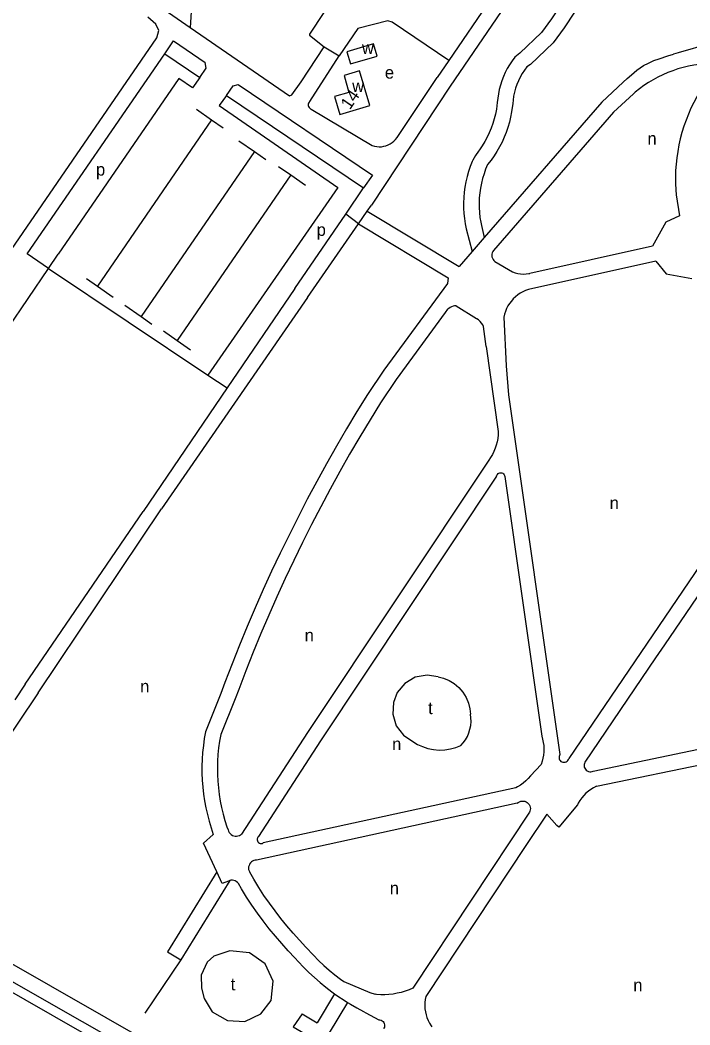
# Model space of a CAD drawing. Extents: x 157155 to 159285, y 385001 to 386651.
# Drawn here: x 158563.8 to 158780.5, y 385278.4 to 385603.8 of the extents above; entities that cross this region are included whole.
import ezdxf

# ---------------------------------------------------------------- set-up
doc = ezdxf.new("R2010")
doc.units = 0
for name, color, linetype in [('BLT_Basislijn', 7, 'Continuous'), ('BLT_Bebouwing', 7, 'Continuous'), ('BLT_Centroide', 7, 'Continuous'), ('BLT_Huisnummer', 7, 'Continuous')]:
    doc.layers.add(name, color=color, linetype=linetype)

msp = doc.modelspace()

# ---------------------------------------------------------------- linework, layer by layer
at = {"layer": 'BLT_Basislijn'}
for p, q in [((158751.68, 385654.34), (158702.89, 385582.36)), ((158602.47, 385612.76), (158618.75, 385601.38)), ((158716.17, 385610.87), (158702.45, 385590.64)), ((158787.14, 385596.2), (158776.65, 385593.14)), ((158610.55, 385592.88), (158621.93, 385585.19)), ((158657.48, 385577.4), (158667, 385592.17)), ((158662.19, 385595.07), (158667, 385592.17)), ((158725.45, 385593.04), (158723.83, 385591.7)), ((158776.65, 385593.14), (158775.15, 385592.7)), ((158702.45, 385590.64), (158698.75, 385585.17)), ((158728.91, 385589.43), (158727.74, 385588.59)), ((158702.89, 385582.36), (158677.42, 385543.88)), ((158685.75, 385565.74), (158698.75, 385585.17)), ((158758.94, 385583.66), (158751.98, 385577.17)), ((158762.2, 385579.88), (158755.75, 385573.89)), ((158751.98, 385577.17), (158713.92, 385533.36)), ((158718.17, 385577.11), (158717.88, 385574.87)), ((158723.15, 385576.76), (158722.81, 385574.03)), ((158620.8, 385574.96), (158625.74, 385571.48)), ((158657.95, 385574.91), (158677.67, 385563.1)), ((158755.75, 385573.89), (158716.92, 385529.2)), ((158625.74, 385571.48), (158588.77, 385517.6)), ((158625.74, 385571.48), (158629.45, 385568.87)), ((158634.58, 385564.7), (158639.59, 385561.17)), ((158639.59, 385561.17), (158602.95, 385507.76)), ((158639.59, 385561.17), (158643.24, 385558.6)), ((158647.41, 385556.36), (158651.33, 385553.6)), ((158716.15, 385558.36), (158715.02, 385556.95)), ((158651.33, 385553.6), (158614.58, 385500.04)), ((158651.33, 385553.6), (158656.07, 385550.26)), ((158676.06, 385541.9), (158677.42, 385543.88)), ((158673.21, 385537.78), (158669.11, 385540.93)), ((158673.21, 385537.78), (158676.06, 385541.9)), ((158676.06, 385541.9), (158705.8, 385524.02)), ((158656.75, 385513.98), (158673.21, 385537.78)), ((158673.21, 385537.78), (158702.3, 385520.29)), ((158713, 385537.22), (158713.92, 385533.36)), ((158708.12, 385536.14), (158710.01, 385528.86)), ((158713.92, 385533.36), (158710.01, 385528.86)), ((158768.43, 385530.57), (158728.67, 385521.7)), ((158572.92, 385523.29), (158576.09, 385528)), ((158710.01, 385528.86), (158705.8, 385524.02)), ((158717.32, 385525.64), (158723.07, 385522.22)), ((158769.51, 385525.69), (158728.23, 385516.48)), ((158559.8, 385503.88), (158572.92, 385523.29)), ((158572.92, 385523.29), (158624.56, 385488.81)), ((158585.21, 385520.11), (158588.77, 385517.6)), ((158588.77, 385517.6), (158593.87, 385514.01)), ((158656.75, 385513.98), (158609.48, 385445.45)), ((158652.62, 385516.8), (158630.77, 385484.66)), ((158597.71, 385511.45), (158602.95, 385507.76)), ((158704.89, 385511.19), (158711.42, 385507.15)), ((158602.95, 385507.76), (158606.37, 385505.35)), ((158701.31, 385509.03), (158685.43, 385487.41)), ((158702.1, 385510.1), (158701.31, 385509.03)), ((158714.53, 385498.09), (158713.75, 385504.51)), ((158610.22, 385503.11), (158614.58, 385500.04)), ((158614.58, 385500.04), (158618.87, 385497.01)), ((158714.53, 385498.09), (158718.47, 385470.52)), ((158624.56, 385488.81), (158630.77, 385484.66)), ((158681.4, 385490.36), (158676.13, 385482.52)), ((158630.77, 385484.66), (158603.58, 385444.67)), ((158685.43, 385487.41), (158680.37, 385479.87)), ((158721.82, 385482.43), (158738.45, 385365.96)), ((158809.08, 385464.65), (158741.28, 385364.66)), ((158715.39, 385461.28), (158656.73, 385373.13)), ((158811.18, 385458.84), (158772.26, 385401.45)), ((158717.94, 385456.07), (158660.93, 385370.42)), ((158720.55, 385455.94), (158732.55, 385371.89)), ((158569.62, 385385.93), (158609.48, 385445.45)), ((158565.46, 385388.72), (158603.58, 385444.67)), ((158772.26, 385401.45), (158769.4, 385397.23)), ((158769.4, 385397.23), (158746.5, 385363.45)), ((158565.46, 385388.72), (158562.09, 385383.69)), ((158569.62, 385385.93), (158528.73, 385325)), ((158628.68, 385385.7), (158623.76, 385373.34)), ((158633.37, 385383.97), (158628.67, 385372.39)), ((158656.73, 385373.13), (158635.45, 385340.18)), ((158749.19, 385360.54), (158800.11, 385371.17)), ((158660.93, 385370.42), (158640.92, 385339.43)), ((158750.22, 385355.65), (158803.67, 385366.81)), ((158732.31, 385362.76), (158728.89, 385359.03)), ((158724.2, 385355.19), (158642.42, 385337.31)), ((158724.58, 385350.15), (158640.3, 385331.74)), ((158744.11, 385349.7), (158738.09, 385342.43)), ((158728.61, 385347.29), (158690.85, 385290.32)), ((158734.16, 385346.61), (158727.43, 385336.47)), ((158727.43, 385336.47), (158695.01, 385287.56)), ((158631.62, 385325.14), (158631.18, 385324.99)), ((158524.7, 385319), (158658.07, 385242.8)), ((158523.9, 385310.24), (158946.21, 385068.98)), ((158656.27, 385303.58), (158658.73, 385300.96)), ((158615.77, 385299.51), (158604.15, 385282.24)), ((158653.86, 385298.85), (158652.69, 385300.09)), ((158665.54, 385288.44), (158659.86, 385279.04)), ((158675.67, 385282.35), (158679.81, 385280.08))]:
    msp.add_line(p, q, dxfattribs=at)
for points in [[(158833.31, 385760.28), (158776.66, 385676.22), (158767.96, 385662.54), (158746.13, 385630.09), (158742.84, 385623.16), (158740.94, 385615.55), (158738.59, 385608.5), (158735.7, 385604.17), (158732.44, 385599.72), (158725.45, 385593.04)], [(158775.15, 385664.52), (158772.15, 385659.8), (158750.49, 385627.6), (158747.57, 385621.47), (158745.74, 385614.16), (158743.12, 385606.29), (158739.8, 385601.3), (158736.21, 385596.41), (158728.91, 385589.43)], [(158649.5, 385655.57), (158622.82, 385616.45), (158621.85, 385614.95), (158619.99, 385611.07), (158619.13, 385606.43), (158618.75, 385601.38)], [(158679.75, 385633.1), (158657.37, 385599.21), (158657.38, 385598.9), (158662.19, 385595.07)], [(158552.82, 385517.63), (158559.78, 385527.78), (158608.05, 385598.05), (158608.71, 385600.34), (158607.67, 385602.42), (158605.06, 385604.69)], [(158702.45, 385590.64), (158684.11, 385603.1), (158682.74, 385603.53), (158673.09, 385601.06), (158667, 385592.17)], [(158618.75, 385601.38), (158650.9, 385579.22), (158651.7, 385579.54), (158654.76, 385583.73), (158662.19, 385595.07)], [(158610.55, 385592.88), (158613.39, 385597)], [(158613.39, 385597), (158623.69, 385590.04)], [(158572.92, 385523.29), (158566.02, 385528.03), (158610.55, 385592.88)], [(158758.94, 385583.66), (158760.13, 385584.83), (158761.54, 385586.02), (158763.35, 385587.51), (158765.48, 385589), (158767.05, 385589.83), (158768.83, 385590.65), (158770.52, 385591.24), (158773.38, 385592.19), (158775.15, 385592.7)], [(158621.93, 385585.19), (158623.96, 385588.19), (158623.69, 385590.04)], [(158723.83, 385591.7), (158722.95, 385590.53), (158722.15, 385589.32), (158721.41, 385588.07), (158720.74, 385586.77), (158720.14, 385585.45), (158719.62, 385584.09), (158719.17, 385582.7), (158718.8, 385581.29), (158718.51, 385579.87), (158718.29, 385578.43), (158718.17, 385577.11)], [(158727.74, 385588.59), (158726.96, 385587.54), (158726.25, 385586.44), (158725.6, 385585.3), (158725.02, 385584.12), (158724.51, 385582.92), (158724.08, 385581.68), (158723.73, 385580.41), (158723.45, 385579.13), (158723.26, 385577.84), (158723.15, 385576.76)], [(158785.26, 385589.51), (158783.5, 385589.35), (158781.76, 385589.12), (158780.03, 385588.8), (158778.31, 385588.4), (158776.62, 385587.93), (158774.95, 385587.38), (158773.3, 385586.76), (158771.68, 385586.06), (158770.1, 385585.29), (158768.56, 385584.44), (158767.05, 385583.53), (158765.59, 385582.55), (158764.17, 385581.51), (158762.81, 385580.4), (158762.2, 385579.88)], [(158787.35, 385585.93), (158786.09, 385584.25), (158784.9, 385582.53), (158783.78, 385580.76), (158782.73, 385578.96), (158781.74, 385577.11), (158780.83, 385575.23), (158779.99, 385573.31), (158779.22, 385571.36), (158778.53, 385569.39), (158777.91, 385567.38), (158777.37, 385565.36), (158776.91, 385563.32), (158776.53, 385561.26), (158776.23, 385559.19), (158776, 385557.11), (158775.86, 385555.02), (158775.79, 385552.93), (158775.81, 385550.84), (158775.9, 385548.75), (158776.02, 385547.18)], [(158621.93, 385585.19), (158619.59, 385581.8), (158615.12, 385584.88), (158576.09, 385528)], [(158630.55, 385579.37), (158632.73, 385582.48), (158634.29, 385582.87)], [(158634.29, 385582.87), (158677.74, 385553.53), (158674.9, 385549.41)], [(158630.55, 385579.37), (158628.23, 385576.07), (158666.57, 385549.54), (158624.56, 385488.81)], [(158630.55, 385579.37), (158674.9, 385549.41)], [(158657.48, 385577.4), (158657.26, 385577.13), (158657.1, 385576.82), (158657.02, 385576.48), (158657.02, 385576.14), (158657.1, 385575.8), (158657.26, 385575.49), (158657.48, 385575.22), (158657.75, 385575.01), (158657.95, 385574.91)], [(158717.88, 385574.87), (158717.58, 385573.3), (158717.19, 385571.75), (158716.73, 385570.22), (158716.19, 385568.72), (158715.57, 385567.25), (158714.89, 385565.8), (158714.13, 385564.4), (158713.3, 385563.03), (158712.41, 385561.71), (158712.13, 385561.33)], [(158722.81, 385574.03), (158722.48, 385572.34), (158722.08, 385570.67), (158721.59, 385569.02), (158721.03, 385567.4), (158720.4, 385565.8), (158719.69, 385564.24), (158718.91, 385562.71), (158718.06, 385561.22), (158717.14, 385559.77), (158716.15, 385558.36)], [(158677.67, 385563.1), (158678.4, 385562.9), (158679.15, 385562.78), (158679.9, 385562.74), (158680.66, 385562.77), (158681.4, 385562.89), (158682.13, 385563.09), (158682.84, 385563.36), (158683.51, 385563.7), (158684.15, 385564.11), (158684.73, 385564.59), (158685.26, 385565.13), (158685.75, 385565.74)], [(158712.13, 385561.33), (158711.15, 385559.87), (158710.25, 385558.38), (158710, 385557.93)], [(158710, 385557.93), (158709.39, 385556.33), (158708.85, 385554.71), (158708.39, 385553.06), (158708.01, 385551.39), (158707.7, 385549.71), (158707.48, 385548.01), (158707.33, 385546.3), (158707.26, 385544.59), (158707.28, 385542.88), (158707.37, 385541.17), (158707.55, 385539.47), (158707.8, 385537.77), (158708.12, 385536.14)], [(158715.02, 385556.95), (158714.4, 385555.48), (158713.87, 385553.99), (158713.4, 385552.46), (158713.02, 385550.92), (158712.71, 385549.36), (158712.48, 385547.78), (158712.34, 385546.2), (158712.27, 385544.61), (158712.28, 385543.02), (158712.37, 385541.43), (158712.54, 385539.85), (158712.79, 385538.28), (158713, 385537.22)], [(158669.11, 385540.93), (158674.9, 385549.41)], [(158776.02, 385547.18), (158777.14, 385540.4), (158772.67, 385538.37), (158768.43, 385530.57)], [(158652.62, 385516.8), (158669.11, 385540.93)], [(158716.92, 385529.2), (158716.68, 385528.82), (158716.51, 385528.4), (158716.41, 385527.96), (158716.39, 385527.51), (158716.45, 385527.06), (158716.59, 385526.63), (158716.8, 385526.23), (158717.08, 385525.87), (158717.32, 385525.64)], [(158769.51, 385525.69), (158772.85, 385521.6), (158781.13, 385520.12)], [(158702.3, 385520.29), (158702.06, 385518.5), (158681.4, 385490.36)], [(158723.07, 385522.22), (158723.93, 385521.93), (158724.81, 385521.72), (158725.71, 385521.58), (158726.61, 385521.53), (158727.52, 385521.55), (158728.42, 385521.66), (158728.67, 385521.7)], [(158728.23, 385516.48), (158727.32, 385516.15), (158726.44, 385515.76), (158725.6, 385515.29), (158724.8, 385514.75), (158724.05, 385514.15), (158723.35, 385513.49), (158722.71, 385512.77), (158722.12, 385512.01), (158721.61, 385511.19), (158721.16, 385510.34), (158720.79, 385509.45), (158720.49, 385508.54), (158720.27, 385507.61)], [(158704.89, 385511.19), (158704.37, 385511.19), (158703.85, 385511.11), (158703.34, 385510.95), (158702.87, 385510.72), (158702.44, 385510.42), (158702.1, 385510.1)], [(158720.27, 385507.61), (158721.05, 385491.76), (158721.82, 385482.43)], [(158713.75, 385504.51), (158713.44, 385505.11), (158713.07, 385505.67), (158712.63, 385506.19), (158712.13, 385506.65), (158711.59, 385507.04), (158711.42, 385507.15)], [(158676.13, 385482.52), (158672.72, 385476.97), (158669.37, 385471.38), (158666.1, 385465.75), (158662.9, 385460.08), (158659.76, 385454.37), (158656.69, 385448.62), (158653.7, 385442.84), (158650.78, 385437.02), (158647.93, 385431.16), (158645.15, 385425.27), (158642.44, 385419.35), (158639.81, 385413.39), (158637.25, 385407.41), (158634.76, 385401.39), (158632.35, 385395.34), (158630.01, 385389.26), (158628.68, 385385.7)], [(158680.37, 385479.87), (158676.98, 385474.35), (158673.65, 385468.79), (158670.39, 385463.18), (158667.2, 385457.54), (158664.08, 385451.86), (158661.04, 385446.14), (158658.06, 385440.38), (158655.15, 385434.58), (158652.32, 385428.75), (158649.55, 385422.89), (158646.86, 385416.99), (158644.25, 385411.06), (158641.7, 385405.1), (158639.23, 385399.11), (158636.84, 385393.08), (158634.52, 385387.03), (158633.37, 385383.97)], [(158718.47, 385470.52), (158718.43, 385469.42), (158718.32, 385468.32), (158718.12, 385467.23), (158717.85, 385466.16), (158717.5, 385465.11), (158717.07, 385464.09), (158716.57, 385463.1), (158716, 385462.16), (158715.39, 385461.28)], [(158717.94, 385456.07), (158718.02, 385456.38), (158718.18, 385456.66), (158718.4, 385456.9), (158718.68, 385457.07), (158718.98, 385457.17), (158719.31, 385457.2), (158719.62, 385457.14), (158719.92, 385457.01), (158720.17, 385456.81), (158720.37, 385456.55), (158720.5, 385456.25), (158720.55, 385455.94)], [(158699.03, 385391.07), (158695.46, 385391.63), (158691.64, 385390.94), (158688.24, 385388.96), (158685.82, 385386.07), (158684.53, 385382.8), (158684.35, 385379.04), (158685.49, 385375.27), (158687.82, 385372.17), (158690.81, 385370.15)], [(158699.03, 385391.07), (158695.46, 385391.63), (158691.64, 385390.94), (158688.24, 385388.96), (158685.82, 385386.07), (158684.53, 385382.8), (158684.35, 385379.04), (158685.49, 385375.27), (158687.82, 385372.17), (158690.81, 385370.15)], [(158699.03, 385391.07), (158700.79, 385390.64), (158702.54, 385389.92), (158704.21, 385388.92), (158705.74, 385387.64), (158707.04, 385386.12), (158708.08, 385384.43), (158708.83, 385382.62), (158709.28, 385380.79), (158709.45, 385378.98)], [(158706.34, 385368.86), (158707.14, 385369.74), (158707.86, 385370.72), (158708.47, 385371.79), (158708.97, 385372.94), (158709.33, 385374.13), (158709.56, 385375.36), (158709.66, 385376.59), (158709.62, 385377.8), (158709.45, 385378.98)], [(158623.76, 385373.34), (158623.37, 385371.12), (158623.06, 385368.89), (158622.83, 385366.64), (158622.68, 385364.4), (158622.61, 385362.14), (158622.62, 385359.89), (158622.71, 385357.64), (158622.88, 385355.39), (158623.12, 385353.15), (158623.45, 385350.92), (158623.86, 385348.7), (158624.35, 385346.5), (158624.91, 385344.32), (158625.55, 385342.16), (158626.26, 385340.03)], [(158628.67, 385372.39), (158628.29, 385370.26), (158628, 385368.11), (158627.79, 385365.96), (158627.66, 385363.8), (158627.6, 385361.64), (158627.63, 385359.48), (158627.74, 385357.32), (158627.92, 385355.16), (158628.19, 385353.02), (158628.53, 385350.88), (158628.96, 385348.76), (158629.46, 385346.65), (158630.04, 385344.57), (158630.7, 385342.51), (158631.04, 385341.52)], [(158732.55, 385371.89), (158732.84, 385370.9), (158733.05, 385369.89), (158733.19, 385368.86), (158733.24, 385367.83), (158733.21, 385366.8), (158733.11, 385365.77), (158732.92, 385364.76), (158732.66, 385363.76), (158732.31, 385362.76)], [(158690.81, 385370.15), (158692.31, 385369.24), (158693.94, 385368.49), (158695.68, 385367.92), (158697.49, 385367.56), (158699.33, 385367.4), (158701.17, 385367.47), (158702.98, 385367.74), (158704.71, 385368.21), (158706.34, 385368.86)], [(158738.45, 385365.96), (158738.27, 385365.65), (158738.16, 385365.31), (158738.13, 385364.96), (158738.18, 385364.6), (158738.31, 385364.27), (158738.51, 385363.98), (158738.77, 385363.73), (158739.08, 385363.55), (158739.42, 385363.44), (158739.77, 385363.42), (158740.12, 385363.47), (158740.46, 385363.59), (158740.75, 385363.79), (158741, 385364.05), (158741.18, 385364.36), (158741.28, 385364.66)], [(158746.5, 385363.45), (158746.33, 385363.08), (158746.24, 385362.68), (158746.24, 385362.27), (158746.31, 385361.87), (158746.45, 385361.49), (158746.67, 385361.15), (158746.95, 385360.85), (158747.29, 385360.61), (158747.66, 385360.45), (158748.06, 385360.36), (158748.47, 385360.35), (158748.87, 385360.42), (158749.19, 385360.54)], [(158728.89, 385359.03), (158728.16, 385358.2), (158727.38, 385357.43), (158726.54, 385356.71), (158725.65, 385356.06), (158724.72, 385355.48), (158724.2, 385355.19)], [(158750.22, 385355.65), (158749.31, 385355.18), (158748.45, 385354.65), (158747.63, 385354.05), (158746.86, 385353.39), (158746.15, 385352.67), (158745.49, 385351.89), (158744.9, 385351.07), (158744.38, 385350.2), (158744.11, 385349.7)], [(158724.58, 385350.15), (158724.92, 385350.44), (158725.31, 385350.66), (158725.73, 385350.82), (158726.17, 385350.89), (158726.62, 385350.88), (158727.06, 385350.8), (158727.47, 385350.63), (158727.85, 385350.4), (158728.19, 385350.1), (158728.46, 385349.75), (158728.67, 385349.35), (158728.8, 385348.93), (158728.86, 385348.48), (158728.84, 385348.04), (158728.74, 385347.6), (158728.61, 385347.29)], [(158738.09, 385342.43), (158737.43, 385342.97), (158734.16, 385346.61)], [(158631.04, 385341.52), (158631.2, 385341.08), (158631.42, 385340.68), (158631.72, 385340.32), (158632.07, 385340.01), (158632.46, 385339.77), (158632.9, 385339.6), (158633.35, 385339.51), (158633.82, 385339.5), (158634.27, 385339.57), (158634.72, 385339.71), (158635.13, 385339.93), (158635.45, 385340.18)], [(158627.45, 385327.91), (158623.1, 385337.27), (158626.26, 385340.03)], [(158640.92, 385339.43), (158640.7, 385339.2), (158640.55, 385338.91), (158640.47, 385338.6), (158640.47, 385338.28), (158640.54, 385337.97), (158640.7, 385337.68), (158640.91, 385337.44), (158641.18, 385337.26), (158641.49, 385337.16), (158641.81, 385337.13), (158642.13, 385337.18), (158642.42, 385337.31)], [(158640.3, 385331.74), (158639.84, 385331.71), (158639.4, 385331.6), (158638.99, 385331.41), (158638.62, 385331.15), (158638.29, 385330.83), (158638.03, 385330.46), (158637.84, 385330.04), (158637.72, 385329.6), (158637.68, 385329.15), (158637.72, 385328.7), (158637.84, 385328.26), (158638.06, 385327.8)], [(158627.45, 385327.91), (158611.48, 385302.07), (158615.77, 385299.51)], [(158631.62, 385325.14), (158615.77, 385299.51)], [(158631.18, 385324.99), (158629.16, 385324.22), (158627.45, 385327.91)], [(158634.39, 385324.15), (158634.09, 385324.49), (158633.73, 385324.78), (158633.33, 385325), (158632.89, 385325.15), (158632.44, 385325.22), (158631.98, 385325.21), (158631.62, 385325.14)], [(158656.27, 385303.58), (158654.15, 385305.82), (158652.08, 385308.11), (158650.08, 385310.46), (158648.13, 385312.85), (158646.25, 385315.3), (158644.43, 385317.8), (158642.68, 385320.34), (158640.99, 385322.92), (158639.37, 385325.55), (158638.06, 385327.8)], [(158652.69, 385300.09), (158650.52, 385302.38), (158648.41, 385304.72), (158646.36, 385307.11), (158644.37, 385309.55), (158642.44, 385312.04), (158640.58, 385314.58), (158638.78, 385317.17), (158637.05, 385319.8), (158635.38, 385322.48), (158634.39, 385324.15)], [(158522.97, 385314.23), (158948.8, 385070.96), (158946.21, 385068.98)], [(158658.73, 385300.96), (158660.36, 385299.29), (158662.06, 385297.68), (158663.81, 385296.13), (158665.61, 385294.65), (158667.46, 385293.22), (158668.47, 385292.48)], [(158653.86, 385298.85), (158655.51, 385297.09), (158657.22, 385295.37), (158658.99, 385293.72), (158660.81, 385292.12), (158662.68, 385290.59), (158664.6, 385289.11), (158665.54, 385288.44)], [(158668.47, 385292.48), (158671.27, 385291.22), (158674.1, 385290.04), (158676.96, 385288.93), (158678.64, 385288.32)], [(158690.85, 385290.32), (158689.62, 385289.78), (158688.36, 385289.32), (158687.08, 385288.93), (158685.77, 385288.62), (158684.45, 385288.39), (158683.12, 385288.24), (158681.78, 385288.17), (158680.45, 385288.18), (158679.11, 385288.27), (158678.64, 385288.32)], [(158665.54, 385288.44), (158666.57, 385287.7), (158668.58, 385286.36), (158669.71, 385285.67)], [(158695.01, 385287.56), (158694.83, 385286.59), (158694.73, 385285.6), (158694.71, 385284.62), (158694.76, 385283.63), (158694.9, 385282.65), (158695.11, 385281.69), (158695.4, 385280.75), (158695.77, 385279.83), (158696.21, 385278.95), (158696.72, 385278.1), (158696.97, 385277.75)], [(158669.71, 385285.67), (158654.67, 385260.78), (158665.39, 385253.7)], [(158669.71, 385285.67), (158670.64, 385285.09), (158672.74, 385283.88), (158674.87, 385282.74), (158675.67, 385282.35)], [(158655.03, 385281.93), (158652.17, 385277.81), (158657.28, 385274.76)], [(158655.03, 385281.93), (158659.86, 385279.04)], [(158679.81, 385280.08), (158680.19, 385280.04), (158680.56, 385279.92), (158680.9, 385279.73), (158681.19, 385279.47), (158681.42, 385279.16), (158681.59, 385278.81), (158681.68, 385278.43), (158681.68, 385278.05), (158681.62, 385277.67), (158681.47, 385277.31), (158681.36, 385277.12)]]:
    msp.add_lwpolyline(points, dxfattribs=at)
msp.add_lwpolyline([(158624.27, 385298.73), (158622.37, 385294.55), (158622.43, 385290.34), (158623.36, 385286.93), (158625.96, 385282.65), (158630.86, 385279.86), (158636.43, 385279.55), (158641.64, 385281.97), (158645.05, 385286.31), (158645.6, 385292.57), (158643.06, 385298.21), (158638.04, 385301.68), (158631.66, 385302.43), (158626.46, 385300.63)], close=True, dxfattribs=at)
at = {"layer": 'BLT_Bebouwing'}
for points in [[(158669.48, 385593.48), (158670.62, 385589.58), (158679.27, 385592.12), (158678.12, 385596.02), (158669.48, 385593.48)], [(158673.63, 385587.28), (158668.59, 385585.8), (158670.18, 385580.36), (158665.48, 385578.98), (158667.17, 385573.2), (158676.93, 385576.07), (158673.63, 385587.28)]]:
    msp.add_lwpolyline(points, dxfattribs=at)

# ---------------------------------------------------------------- texts
at = {"layer": 'BLT_Centroide'}
for s, p in [('w', (158674.37, 385592.81)), ('e', (158681.79, 385584.8)), ('w', (158671.2, 385580.47)), ('n', (158766.75, 385563.42)), ('p', (158588.33, 385553.4)), ('p', (158659.72, 385533.89)), ('n', (158754.52, 385445.42)), ('n', (158655.84, 385402.57)), ('n', (158602.62, 385386.05)), ('t', (158695.79, 385379.03)), ('n', (158684.14, 385367.37)), ('n', (158683.38, 385320.69)), ('t', (158631.92, 385289.59)), ('n', (158762.16, 385289.31))]:
    msp.add_text(s, height=4, dxfattribs=at).set_placement(p)
at = {"layer": 'BLT_Huisnummer'}
msp.add_text('14', height=4, rotation=55.5018, dxfattribs=at).set_placement((158670.47, 385574.51))

doc.saveas('drawing.dxf')
